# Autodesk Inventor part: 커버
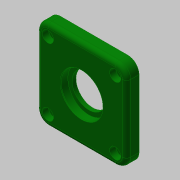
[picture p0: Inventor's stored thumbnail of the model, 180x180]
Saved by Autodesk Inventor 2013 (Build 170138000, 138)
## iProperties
Created: 2019-09
Part Number: 커버
Material: 알루미늄 6061
Document SubType Name: Modeling
Designer: mduedu
Density: 1 g/cm^3
Author: mduedu
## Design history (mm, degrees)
sketch "스케치1"
  geometry: L1 (-32, -32)-(32, -32); L2 (32, -32)-(32, 32); L3 (32, 32)-(-32, 32); L4 (-32, 32)-(-32, -32); L5 (-32, -32)-(32, 32); L6 (32, -32)-(-32, 32); 1 further point
  constraints: 12 end point, 2 midpoint, 2 parallel, 1 horizontal, 1 perpendicular
  dimensions: "d44" = 64 distance of L3.end L2.end; "d45" = 64 distance of L2.end L1.end
extrude "돌출1" new body sketch "스케치1" distance "d1" = 9; taper "d2" = 0 deg
sketch "스케치2"
  geometry: C1 r 21 at (0, 0); 1 further point
  constraints: 1 centre point, 1 coincident
  dimensions: "d3" = 42 diameter of C1
extrude "돌출2" join sketch "스케치2" distance "d4" = 3; taper "d5" = 0 deg
hole "구멍1" diameter "d8" = 24; stored, may be unused: countersink angle "d12" = 90 deg, drill point angle "d14" = 118 deg; dims "d9" = 6, "d10" = 30, "d11" = 5.2, "d13" = 8, "d46" = 10, "d47" = 10
hole "구멍2" diameter "d17" = 37; stored, may be unused: countersink angle "d21" = 90 deg, drill point angle "d23" = 0 deg; dims "d15" = 10, "d16" = 10, "d18" = 6, "d19" = 30, "d20" = 5.2, "d22" = 4
fillet "모깎기1" dims "d24" = 3
fillet "모깎기4" dims "d48" = 8
fillet "모깎기2" dims "d25" = 3
chamfer "모따기1" distance "d27" = 0.5; stored, may be unused: second distance "d28" = 2, angle "d29" = 30 deg
chamfer "모따기2" distance "d30" = 1; stored, may be unused: second distance "d31" = 2, angle "d32" = 30 deg
sketch "스케치4"
  geometry: A1 r 8 centre (-24, 24) between (-24, 32) and (-32, 24) reference; A2 r 8 centre (24, 24) between (32, 24) and (24, 32) reference; A3 r 8 centre (24, -24) between (24, -32) and (32, -24) reference; A4 r 8 centre (-24, -24) between (-32, -24) and (-24, -32) reference; 5 further points
  constraints: 4 coincident
hole "구멍4" sketch "스케치4" at (-24, 24), (24, 24), (24, -24), (-24, -24) diameter "d49" = 4.5; stored, may be unused: countersink angle "d53" = 90 deg, drill point angle "d55" = 118 deg; dims "d50" = 6, "d51" = 8, "d52" = 4.4, "d54" = 8
node "솔리드1"
